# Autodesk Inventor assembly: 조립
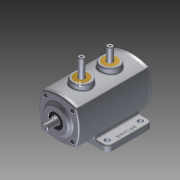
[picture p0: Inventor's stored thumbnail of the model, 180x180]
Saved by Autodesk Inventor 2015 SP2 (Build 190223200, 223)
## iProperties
Created: 2015-06
Part Number: 조립
Document SubType Name: Assembly
Designer: AMC
Author: AMC
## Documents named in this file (12)
- C:\Users\AMC\Desktop\350620V1009\조립.iam
- C:\Users\AMC\Desktop\350620V1009\M4-소켓머리.ipt
- C:\Users\AMC\Desktop\350620V1009\뒷커버.ipt
- C:\Users\AMC\Desktop\350620V1009\베어링 6203.ipt
- C:\Users\AMC\Desktop\350620V1009\본체.ipt
- C:\Users\AMC\Desktop\350620V1009\부시.ipt
- C:\Users\AMC\Desktop\350620V1009\슬라이더.ipt
- C:\Users\AMC\Desktop\350620V1009\앞커버.ipt
- C:\Users\AMC\Desktop\350620V1009\오일실.ipt
- C:\Users\AMC\Desktop\350620V1009\축.ipt
- C:\Users\AMC\Desktop\350620V1009\스프링.ipt
- C:\Users\AMC\Desktop\350620V1009\스프링11.ipt
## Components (11 placed, 3 different names)
1. 7-베어링 6203:1
2. 8-오일실:1
3. 7-베어링 6203:2
4. 9-M4-소켓머리:1
5. 9-M4-소켓머리:3
6. 9-M4-소켓머리:4
7. 9-M4-소켓머리:5
8. 9-M4-소켓머리:2
9. 9-M4-소켓머리:6
10. 9-M4-소켓머리:7
11. 9-M4-소켓머리:8
